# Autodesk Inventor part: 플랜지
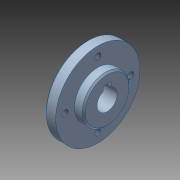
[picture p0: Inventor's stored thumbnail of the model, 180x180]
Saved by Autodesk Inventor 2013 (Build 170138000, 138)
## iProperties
Created: 2024-02
Part Number: 플랜지
Material: 강철, 탄소
Document SubType Name: Modeling
Designer: mdu-01
Density: 1 g/cm^3
Author: mdu-01
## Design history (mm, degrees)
sketch "스케치1"
  geometry: L1 (0, 0)-(22, 0); L2 (0, -6.5)-(0, -11); L3 (0, -11)-(9, -11); L4 (9, -11)-(9, -26); L5 (10, -27)-(16, -27); L6 (16, -27)-(16, -15); L7 (16, -15)-(21, -15); L8 (22, -14)-(22, -6.5); L9 (22, -6.5)-(0, -6.5); L10 (21, -15)-(22, -14); L11 (9, -26)-(10, -27); L12 (0, 0)-(0, 8.8); L13 (0, 8.8)-(22, 8.8); L14 (22, 8.8)-(22, 0); 2 further points
  constraints: 28 end point, 6 parallel, 6 point on line, 4 perpendicular, 1 horizontal, 1 vertical
  dimensions: "d0" = 22 distance of L1.start L1.end; "d1" = 54 diameter of L5 L1; "d2" = 22 diameter of L3 L1; "d3" = 13 diameter of L9 L1; "d4" = 9 distance between parallel lines of L4 L2; "d5" = 6 distance between parallel lines of L8 L6; "d6" = 30 diameter of L7 L1; "d7" = 1 distance of L7.end point (22, -15); "d8" = 1 distance of L8.start point (22, -15) (= d7); "d9" = 1 distance of L4.end point (9, -27) (= d7); "d10" = 1 distance of L5.start point (9, -27) (= d9); "d11" = 15.3 distance between parallel lines of L13 L9
revolve "회전1" stored, may be unused: angle "d12" = 90 deg
extrude "돌출1" cut sketch "스케치1" stored distance "d13" = 5; taper "d14" = 0 deg
chamfer "모따기1" distance "d15" = 1; stored, may be unused: second distance "d16" = 2, angle "d17" = 45 deg
sketch "스케치2" dims "d18" = 42
  geometry: 3 further points
  constraints: 2 vertical alignment, 1 coincident, 2 other
hole "구멍1" sketch "스케치2" at (0, 21) diameter "d20" = 4.134; stored, may be unused: countersink angle "d24" = 90 deg, drill point angle "d26" = 118 deg; dims "d21" = 6, "d22" = 4, "d23" = 2, "d25" = 8
node "솔리드1"
pattern_circular "원형 패턴1" dims angle "d28" = 360 deg
